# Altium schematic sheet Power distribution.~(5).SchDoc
size A3; SheetNumber: 4; SheetTotal: 4
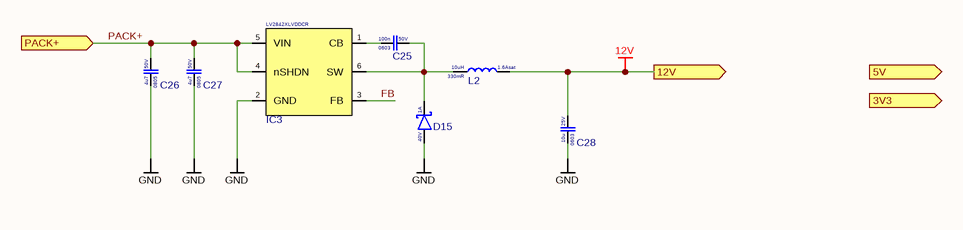
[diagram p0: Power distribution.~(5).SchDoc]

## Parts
C25  Voltage Rating: 50V  Case Code (Imperial): 0603  Capacitance: 100n  [CAP 0603]  (hidden comment: CC0603KRX7R9BB104)
C26  Voltage Rating: 50V  Case Code (Imperial): 0805  Capacitance: 4u7  [Cap_0805]  (hidden comment: CL21A475KBQNNNE)
C27  Voltage Rating: 50V  Case Code (Imperial): 0805  Capacitance: 4u7  [Cap_0805]  (hidden comment: CL21A475KBQNNNE)
C28  Voltage Rating: 25V  Case Code (Imperial): 0603  Capacitance: 10u  [CAP 0603]  (hidden comment: CL10A106MA8NRNC)
D15  Forward Current: 1A  Reverse Voltage: 40V  [SOD-323]  (hidden comment: 1N5819WS)
IC3  LV2842XLVDDCR  [SOT-23-6]
L2  Resistance: 330mR  Saturation current: 1.6Asat  Inductance: 10uH  [IND 1008]  (hidden comment: FTC252012S100MBCA)

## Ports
3V3 (out, see Arhitecture[5C]), 5V (out, see Arhitecture[5C]), 12V (out, see Arhitecture[5C], Charger[1A]), PACK+ (in, see Arhitecture[6C], Battery level indicator[3B], Charger[8A])

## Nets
12V: C28.2 L2.2 ; port 12V
GND: C26.1 C27.1 C28.1 D15.A IC3.2(GND)
FB: IC3.3(FB)
PACK+: C26.2 C27.2 IC3.4(nSHDN) IC3.5(VIN) ; port PACK+
NetC25_1: C25.1 IC3.1(CB)
NetC25_2: C25.2 D15.K IC3.6(SW) L2.1

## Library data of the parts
C25 = CC0603KRX7R9BB104: Cap 100nF 50V 0603 X7R; Manufacturer: Yageo
C26 C27 = CL21A475KBQNNNE: Cap 4.7uF 50V 0805 X5R; Manufacturer: Samsung
C28 = CL10A106MA8NRNC: Cap 10uF 25V 0603 X5R; Manufacturer: Samsung
D15 = 1N5819WS: Schottky 40V 1A 600mVf SOD-323; Manufacturer: Guangdong Hottech
IC3 = LV2842XLVDDCR: Step-down converter 4~40Vin 600mAout Adjustible SOT23-6; Manufacturer: Texas Instruments
L2 = FTC252012S100MBCA: Inductor 10uH 1.6Asat 330mR; Manufacturer: cjiang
